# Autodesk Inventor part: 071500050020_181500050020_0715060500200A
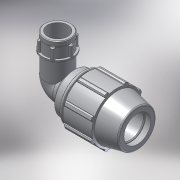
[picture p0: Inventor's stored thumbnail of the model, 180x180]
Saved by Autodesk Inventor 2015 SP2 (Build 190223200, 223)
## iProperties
Created: 2017-02
Part Number: 071500050020_181500050020_0715060500200A
Material: PVC-Piping
Description: PLASSON 90° ELBOW FEMALE ADAPTOR 50-2"
Document SubType Name: Modeling
Designer: KIM
Mass: 92.6774 g
Surface Area: 199.44 cm^2
Volume: 66.1981 cm^3
Density: 1.4 g/cm^3
Appearance: Smooth - White
Author: KIM
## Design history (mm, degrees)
derived "07150.ipt"
feature "Solid1::07150.ipt"
tag "TaggingFeature1"
body "Solid1"
other parameters: "d4" = 11.5, "d5" = 34.5, "d7" = 96, "d9" = 19.71429, "d11" = 4.6, "d13" = 120 deg, "d15" = 12 deg, "d16" = 83.52, "d18" = 2.5, "d19" = 35 deg, "d20" = 17.5 deg, "d21" = 89.28, "d23" = 0, "d25" = 360 deg, "d27" = 1.92, "d33" = 1, "d42" = 51.06, "d43" = 2.88, "d46" = 1.5, "d51" = 138, "d68" = 4.6, "d72" = 85, "d73" = 73.6528, "d75" = 84.70072, "d76" = 56.656, "d77" = 33, "d79" = 22.6624, "d80" = 1.69968, "d83" = 0, "d84" = 0, "d91" = 76.8, "d93" = 93, "d94" = 56.656, "d95" = 39.6592, "d96" = 13.8, "d97" = 50 deg, "d98" = 50.9904, "d99" = 0.5, "d100" = 0.5, "d101" = 10, "d102" = 73.6528, "d103" = 25.5, "d104" = 0, "d108" = 360 deg, "d110" = 2.20958, "E_" = 96, "A_" = 138, "l_" = 93, "A_1" = 85, "Rp_" = 56.656, "d105" = 11.04792
